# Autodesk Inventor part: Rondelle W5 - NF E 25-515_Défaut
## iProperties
Shininess: 64.0
Length Units: 11269
Angle Units: 11279
Time Units: 11290
Mass Units: 11283
Length Display Precision: 3
Angle Display Precision: 2
Compacted: True
Part Number: Rondelle W5 - NF E 25-515_Défaut
Document SubType Name: Modeling
Created: 2006-01
Material: Par défaut
Designer: riri
Density: 0.0
Volumn: 0.0
Area: 0.0
PropertySet Name: Model Information
Control State: 0
Master: False
Checked Out: False
Author: riri
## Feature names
1. Base1
